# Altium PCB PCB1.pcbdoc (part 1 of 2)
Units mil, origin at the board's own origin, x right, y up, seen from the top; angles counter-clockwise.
Board outline 4100 x 4075 mil, 2 copper layers (Top Layer, Bottom Layer); 99 components, 67 nets, 330 pads, 1473 vias.
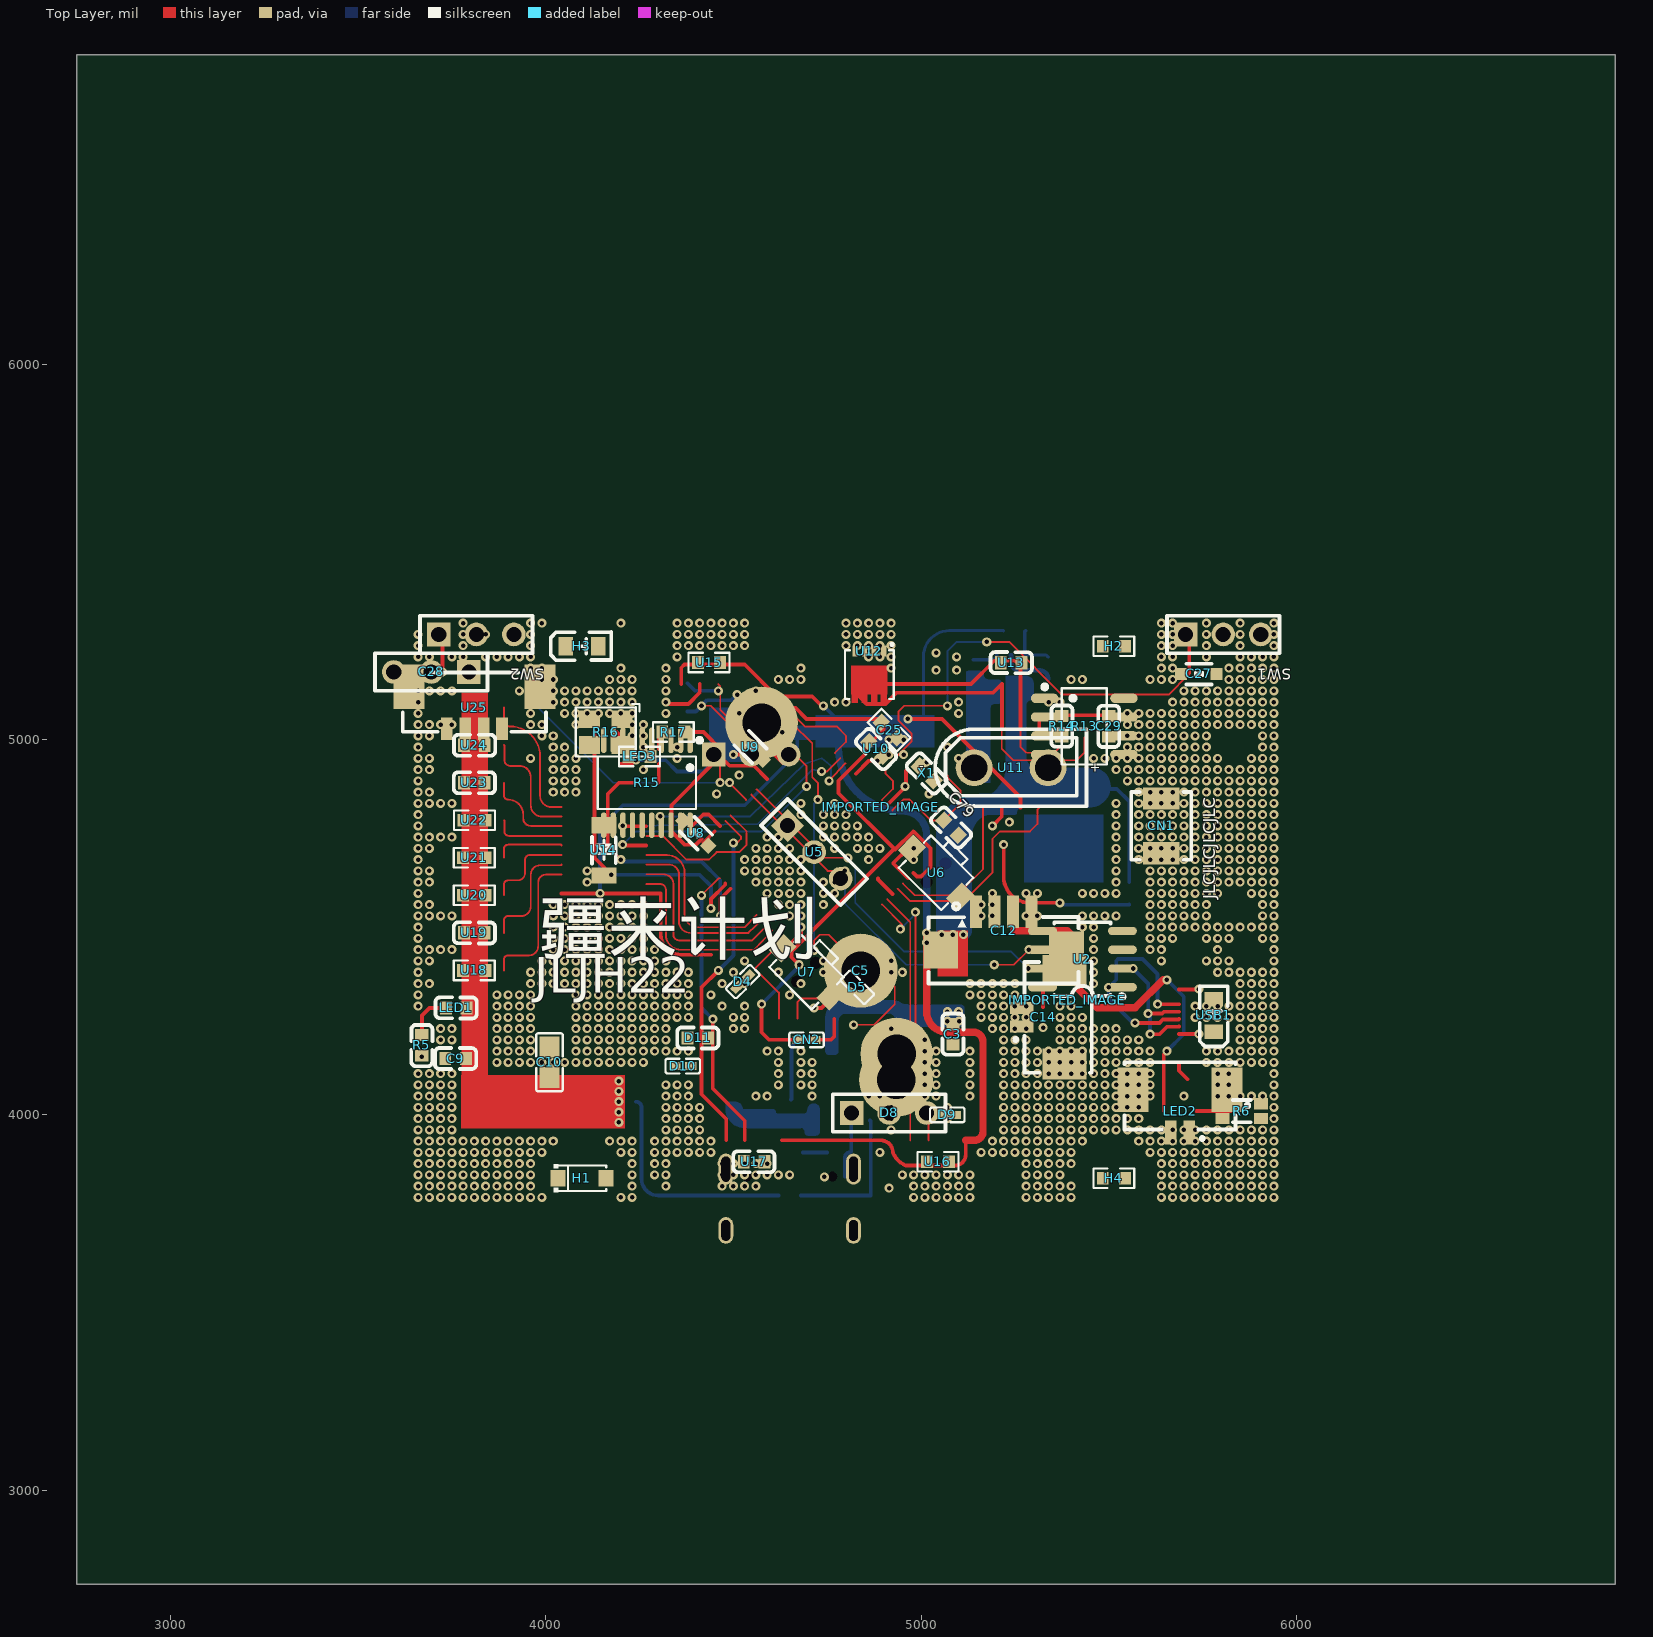
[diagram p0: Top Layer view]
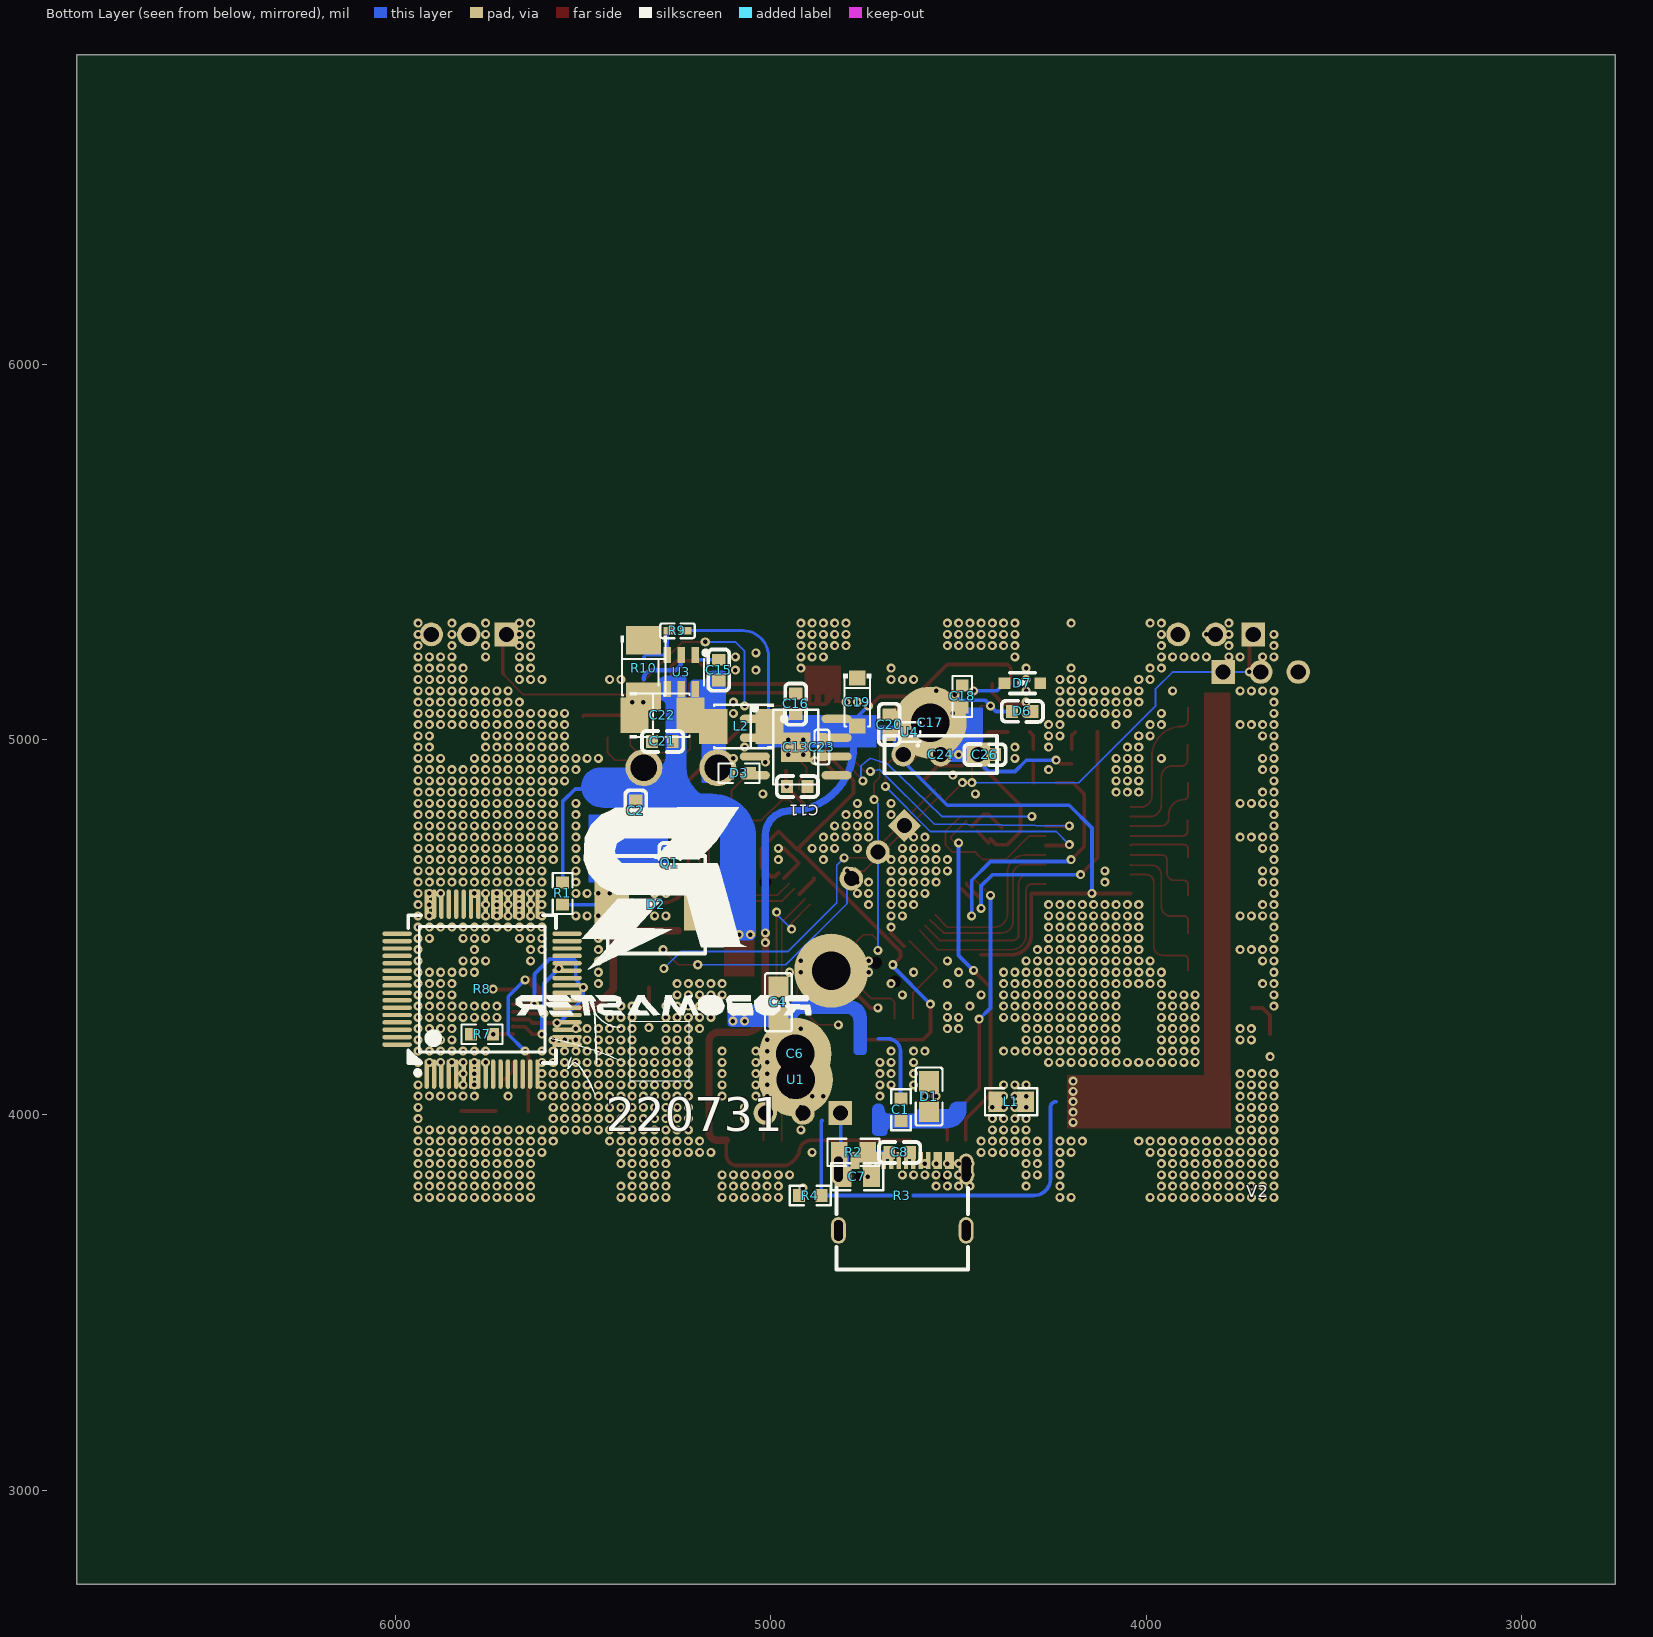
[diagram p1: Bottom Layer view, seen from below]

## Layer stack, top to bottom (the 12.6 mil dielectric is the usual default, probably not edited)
Top Solder: solder mask 0.4, Solder Resist, Dk 3.5
Top Layer: signal copper 1.4
Dielectric 1: dielectric 12.6, FR-4, Dk 4.8
Bottom Layer: signal copper 1.4
Bottom Solder: solder mask 0.4, Solder Resist, Dk 3.5

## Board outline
6850,2750 2750,2750 2750,6825 6850,6825

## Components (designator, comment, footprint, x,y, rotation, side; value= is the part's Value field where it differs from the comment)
C1 "CC0603KRX7R9BB104" R0603 4653.7,4013.7 r270 bottom
C2 "CL10B104KC8NNNC" C0603 5360,4810 r90 bottom
C3 "VT1E101M-CRE54" C0603 5085,4215 r270 top
C4 "CC0603KRX7R9BB104" C0805 4980,4300 r270 bottom
C5 "CL10B104KC8NNNC" M2.5#1 4885,4430 r225 top
C6 "0603B822J500CT" M2.5#2 4935,4162.44 r90 bottom
C7 "CC0603GRNPO9BN100" R0805 4770,3835 r0 bottom
C8 "CL10B102KB8NNNC" C0603 4657.44,3900 r0 bottom
C9 "CC0603KRX7R9BB104" C0603 3760,4150 r0 top
C10 "VT1E101M-CRE54" C0805 4010,4140 r90 top
C11 "0603CG200G500NT" C0603 4930,4875 r0 bottom
C12 "TCC0603X7R104K500CT" CONN-SMD_4P-P1.25_SHOUHAN_1.25-4PWTDK 5220,4490 r0 top
C13 "GRT188C80J226ME13D" SOIC-8_L5.0-W4.0-P1.27-LS6.0-BL-EP2.0 4934.03,4979.87 r270 bottom
C14 "TCC0603X7R104K500CT" CONN-SMD_2P-P1.25_SHOU_1.25-2PWTDK 5325,4260 r90 top
C15 "CL10B104KC8NNNC" C0603 5139.03,5184.87 r270 bottom
C16 "GRM155R71E104KE14D" C0603 4934.03,5094.87 r90 bottom
C17 "CGA2B3X7R1V104MT0Y0F" M2.5#2 4575,5045 r270 bottom
C18 "TC211B106K025Y" R0603 4490,5114.8 r270 bottom
C19 "TC211B106K025Y" SOD-123_L2.7-W1.8-LS3.7-RD 4770,5100 r270 bottom
C20 "CGA2B3X7R1V104MT0Y0F" C0603 4685,5040 r270 bottom
C21 "GRM188C81E475KE11D" C0603 5289.03,4994.87 r0 bottom
C22 "CL10B104KC8NNNC" CAP-SMD_L3.5-W2.8-R-RD 5289.03,5064.87 r0 bottom
C23 "GCM1885C2A220JA16D" C0402 4864.03,4979.87 r270 bottom
C24 "0603" HDR-TH_3P-P2.54-V-M_C9900004029 4547.56,4960 r180 bottom
C25 "0603" R0603 4915,5025 r135 top
C26 "0603" C0603 4430,4960 r0 bottom
C27 "100nF" SOD-323_L1.7-W1.3-LS2.5-BI 5740,5175 r180 top
C28 "100nF" HDR-TH_3P-P2.54-V-M_C9900004029 3695,5180 r0 top
C29 "CL10B104KC8NNNC" C0603 5500,5035 r270 top
C79 "0603CG200G500NT" C0603 5080,4765 r315 top
CN1 "XT30PW-M" IND-SMD_L4.5-W4.0-1 5640,4770 r90 top
CN2 "X9821WVS-04-9TSN" C0402 4695,4200 r0 top
D1 "DSK310" C0805 4578.7,4048.7 r90 bottom
D2 "ZMM9V1" IND-SMD_L6.6-W6.6 5305,4560 r180 bottom
D3 "DSK310" R0603 5085,4910 r180 bottom
D4 "PESD5V0L1BA" C0402 4525,4355 r225 top
D5 "PESD5V0L1BA" C0402 4830,4340 r315 top
D6 "PESD5V0L1BA" C0603 4330,5075 r180 bottom
D7 "PESD5V0L1BA" SOD-323_L1.7-W1.3-LS2.5-BI 4330,5150 r180 bottom
D8 "PESD5V0L1BA" HDR-TH_3P-P2.54-V-M_C9900004029 4915,4005 r180 top
D9 "PESD5V0L1BA" C0402 5070,4000 r0 top
D10 "PESD5V0L1BA" C0402 4365,4130 r180 top
D11 "PESD5V0L1BA" C0603 4405,4205 r180 top
H1 "M2.5_M2.5" SOD-123_L2.7-W1.8-LS3.7-RD 4096.34,3831.34 r0 top
H2 "M2.5_M2.5" R0603 5513.66,5248.66 r0 top
H3 "M2.5_M2.5" LED0805-RD_RED 4096.34,5248.66 r0 top
H4 "M2.5_M2.5" R0603 5513.66,3831.34 r0 top
IMPORTED_IMAGE "IMPORTED_IMAGE" IMPORTED_IMAGE 5390,4305 r0 top
IMPORTED_IMAGE "IMPORTED_IMAGE" IMPORTED_IMAGE 4892.04,4820.19 r0 top
L1 "SMMS0630-6R8M" R0805 4360,4035 r180 bottom
L2 "MCS0420-4R7MPN2" CAP-SMD_L3.5-W2.8-R-RD 5079.03,5034.87 r180 bottom
LED1 "NCD0805R1" C0603 3761.69,4285 r0 top
LED2 "NCD0805R1" CONN-SMD_2P-P1.25_SHOU_1.25-2PWTDK 5690,4010 r180 top
LED3 "HL-PCF-3216S39FU70GH203BC-A" R0603 4250,4955 r0 top
Q1 "WSD3066DN33" C0603 5269.31,4669.9 r90 bottom
R1 "AR03BTD1002" R0603 5555,4590 r90 bottom
R2 "RS-03K473JT" R0805 4780,3900 r180 bottom
R3 "TC0325B4022T5E" USB-C-SMD_TYPE-C16PIN 4650,3785 r180 bottom
R4 "RMC06037.68K1%N" R0603 4895.34,3785 r180 bottom
R5 "RMC06035.1K1%N" C0603 3670,4185 r90 top
R6 "RMC06035.1K5%N" LED-SMD_4P-L3.2-W1.5-BL 5854.66,4010 r180 top
R7 "RMC06035.1K1%N" R0603 5769.66,4215 r180 bottom
R8 "RMC06035.1K1%N" LQFP-64_L10.0-W10.0-P0.50-LS12.0-BL 5769.66,4335 r180 bottom
R9 "TC0325B4022T5E" C0402 5249.03,5289.87 r180 bottom
R10 "RMC06037.68K1%N" CAP-SMD_L3.5-W2.8-R-RD 5339.03,5189.87 r90 bottom
R13 "CR0603JA0560G" SOP-8_L4.9-W3.9-P1.27-LS6.0-BL 5435,5035 r270 top
R14 "CR0603JA0560G" C0603 5375,5035.34 r270 top
R15 "ACPP0603 51R B" TSSOP-20_L6.5-W4.4-P0.65-LS6.4-BL 4269.66,4885 r180 top
R16 "ACPP0603 51R B" OSC-SMD_4P-L3.2-W2.5-BL 4159.66,5020 r180 top
R17 "ACPP0603 51R B" R0603 4340,5020 r0 top
SW1 "YD-3410" HDR-TH_3P-P2.54-V-M_C9900004029 5805,5280 r180 top
SW2 "YD-3410" HDR-TH_3P-P2.54-V-M_C9900004029 3815,5280 r180 top
U1 "TPS54531DDAR" M2.5#3 4788.7,4093.7 r0 bottom
U2 "CH340N" SOIC-8_L5.0-W4.0-P1.27-LS6.0-BL 5430,4415 r90 top
U3 "RY8411" SOT-23-6_L2.9-W1.6-P0.95-LS2.8-TL 5239.03,5179.87 r270 bottom
U4 "SK6019AD4-33" XDFN-4_L1.0-W1.0-P0.65-BL-EP 4630,5020 r90 bottom
U5 "STM32L431RCT6" HDR-TH_3P-P2.54-V-M_C9900004029 4715,4700 r135 top
U6 "CAP,MLCC,X7R,100nF,10V,10%,SMD0402,ROHS" SW-SMD_L3.9-W2.9-LS4.8-EH-A 5040,4645 r135 top
U7 "CAP,MLCC,X7R,100nF,10V,10%,SMD0402,ROHS" SW-SMD_L3.9-W2.9-LS4.8-EH-A 4694.83,4380.17 r135 top
U8 "CAP,MLCC,X7R,100nF,10V,10%,SMD0402,ROHS" SOD-323_L1.7-W1.3-LS2.5-BI 4400,4750 r315 top
U9 "CAP,MLCC,X7R,100nF,10V,10%,SMD0402,ROHS" SOD-323_L1.7-W1.3-LS2.5-BI 4545,4980 r315 top
U10 "CAP,MLCC,X7R,100nF,10V,10%,SMD0402,ROHS" C0603 4880,4975 r135 top
U11 "TJA1040T/CM,118" CONN-TH_XT30UPB-M 5240,4925 r0 top
U12 "1.25-2PWTDK" DFN-8_L3.3-W3.3-P0.65-BL 4862.1,5205 r180 top
U13 "1.25-2PWTDK" C0603 5240,5205 r180 top
U14 "74HC245PW" LL-34_L3.5-W1.5-RD 4155,4705 r90 top
U15 "1.25-4PWTDK" R0603 4435,5205 r180 top
U16 "1.25-4PWTDK" R0603 5045,3875 r0 top
U17 "1.25-4PWTDK" C0603 4555,3875 r0 top
U18 "3pin插件排针" R0603 3809.64,4385 r180 top
U19 "3pin插件排针" C0603 3809.64,4485 r180 top
U20 "3pin插件排针" R0603 3809.64,4585 r180 top
U21 "3pin插件排针" R0603 3809.64,4685 r180 top
U22 "3pin插件排针" R0603 3810,4785 r180 top
U23 "3pin插件排针" C0603 3809.64,4885 r180 top
U24 "3pin插件排针" C0603 3810,4985 r180 top
U25 "3pin插件排针" CONN-SMD_4P-P1.25_X9821WVS-04-9TSN 3810,5085 r180 top
USB1 "TYPE-C 16PIN 3MD(385)" LED0805-RD_RED 5780,4265 r90 top
X1 "X32258MOB4SI" C0603 5015,4910 r135 top

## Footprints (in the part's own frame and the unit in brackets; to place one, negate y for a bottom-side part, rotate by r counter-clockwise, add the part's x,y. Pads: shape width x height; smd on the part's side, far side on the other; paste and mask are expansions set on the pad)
C0402 [mm]
  rect 0.79x0.54 smd: 1(-0.545,0) 2(0.545,0)
  silkscreen extent -1.17,-0.5 1.17,0.5
C0603 [mm]
  rect 0.8x0.9 smd: 1(-0.7,0) 2(0.7,0)
  silkscreen extent -1.41,-0.71 1.39,0.72
C0805 [mm]
  rect 1.41x1.35 smd: 1(-1.03,0) 2(1.03,0)
  silkscreen extent -1.96,-0.9 1.96,0.9
CAP-SMD_L3.5-W2.8-R-RD [mil]
  rect 74.8x93.5 smd: 1(74.8,0) 2(-74.7,0)
  silkscreen extent -72,-61 87,61
CONN-SMD_2P-P1.25_SHOU_1.25-2PWTDK [mm]
  rect 0.8x1.6 smd: 1(-0.625,1.45) 2(0.625,1.45)
  rect 2.1x3 smd: 3(3.175,-1.45) 4(-3.175,-1.45)
  silkscreen extent -3.75,-3.3 3.75,1.95
CONN-SMD_4P-P1.25_SHOUHAN_1.25-4PWTDK [mm]
  rect 0.8x2.2 smd: 1(-1.875,1.3) 2(-0.625,1.3) 3(0.625,1.3) 4(1.875,1.3)
  rect 2.35x2.5 smd: 5(4.255,-1.3) 6(-4.255,-1.3)
  silkscreen extent -5.08,-3.55 5.06,1.88
CONN-SMD_4P-P1.25_X9821WVS-04-9TSN [mil]
  rect 31.5x59.1 smd: 1(-73.8,56.1) 2(-24.6,56.1) 3(24.6,56.1) 4(73.8,56.1)
  rect 82.7x118.1 smd: 5(174.2,-56.1) 6(-174.2,-56.1)
  silkscreen extent -191,-94 191,64
CONN-TH_XT30UPB-M [mil]
  round 98.4 hole 70.9: 1(-98.4,0) 2(98.4,0)
  silkscreen extent -202,-102 201,102
DFN-8_L3.3-W3.3-P0.65-BL [mm]
  rect 0.35x0.75 smd: 1(-0.975,-0.78) 2(-0.325,-0.78) 3(0.325,-0.78) 4(0.975,-0.78)
  Top Layer region: -1.222,0.201 -1.222,2.129 -1.174,2.129 -1.174,2.73 -0.773,2.73 -0.773,2.129 -0.524,2.129 -0.524,2.73 -0.123,2.73 -0.123,2.129 0.126,2.129 0.126,2.73 0.528,2.73 0.528,2.129 0.777,2.129 0.777,2.73 0.777,2.129 0.777,2.73 1.178,2.73 1.178,2.129 1.226,2.129 1.226,0.201
  silkscreen extent -1.65,-1.27 1.65,2.46
HDR-TH_3P-P2.54-V-M_C9900004029 [mil]
  rect 63x63 hole 40.2: 1(100,0)
  round 63 hole 40.2: 2(0,0) 3(-100,0)
  silkscreen extent -150,-50 150,50
IMPORTED_IMAGE [mil]
IND-SMD_L4.5-W4.0-1 [mil]
  rect 59.1x98.4 smd: 1(-72.8,0) 2(72.8,0)
  silkscreen extent -90,-80 90,80
IND-SMD_L6.6-W6.6 [mil]
  rect 92.5x137.8 smd: 1(-119.5,0) 2(119.5,0)
  silkscreen extent -130,-130 130,130
LED0805-RD_RED [mm]
  rect 1x1.25 smd: 1(-1.1,0) 2(1.1,0)
  silkscreen extent -2.1,-0.95 1.98,0.96
LED-SMD_4P-L3.2-W1.5-BL [mm]
  rect 0.95x0.75 smd: 1(1.3,-0.5) 2(-1.3,-0.5) 3(-1.3,0.5) 4(1.3,0.5)
  silkscreen extent -0.59,-0.76 0.59,0.75
LL-34_L3.5-W1.5-RD [mil]
  rect 43.3x66.9 smd: 1(-66.9,0) 2(66.9,0)
  silkscreen extent -35,-32 35,32
LQFP-64_L10.0-W10.0-P0.50-LS12.0-BL [mm]
  oval 0.3x2 smd: 1(-3.75,-5.75) 2(-3.25,-5.75) 3(-2.75,-5.75) 4(-2.25,-5.75) 5(-1.75,-5.75) 6(-1.25,-5.75) 7(-0.75,-5.75) 8(-0.25,-5.75) 9(0.25,-5.75) 10(0.75,-5.75) 11(1.25,-5.75) 12(1.75,-5.75) 13(2.25,-5.75) 14(2.75,-5.75) 15(3.25,-5.75) 16(3.75,-5.75) 33(3.75,5.75) 34(3.25,5.75) 35(2.75,5.75) 36(2.25,5.75) 37(1.75,5.75) 38(1.25,5.75) 39(0.75,5.75) 40(0.25,5.75) 41(-0.25,5.75) 42(-0.75,5.75) 43(-1.25,5.75) 44(-1.75,5.75) 45(-2.25,5.75) 46(-2.75,5.75) 47(-3.25,5.75) 48(-3.75,5.75)
  oval 2x0.3 smd: 17(5.75,-3.75) 18(5.75,-3.25) 19(5.75,-2.75) 20(5.75,-2.25) 21(5.75,-1.75) 22(5.75,-1.25) 23(5.75,-0.75) 24(5.75,-0.25) 25(5.75,0.25) 26(5.75,0.75) 27(5.75,1.25) 28(5.75,1.75) 29(5.75,2.25) 30(5.75,2.75) 31(5.75,3.25) 32(5.75,3.75) 49(-5.75,3.75) 50(-5.75,3.25) 51(-5.75,2.75) 52(-5.75,2.25) 53(-5.75,1.75) 54(-5.75,1.25) 55(-5.75,0.75) 56(-5.75,0.25) 57(-5.75,-0.25) 58(-5.75,-0.75) 59(-5.75,-1.25) 60(-5.75,-1.75) 61(-5.75,-2.25) 62(-5.75,-2.75) 63(-5.75,-3.25) 64(-5.75,-3.75)
  silkscreen extent -5,-5.79 5,5
M2.5#1 [mm]
  round 5 hole 2.6: 1(1.645,0)
M2.5#2 [mm]
  round 4.9 hole 2.6: 1(0,0)
M2.5#3 [mm]
  round 5 hole 2.6: 1(3.677,0)
OSC-SMD_4P-L3.2-W2.5-BL [mm]
  rect 1.4x1.2 smd: 1(-1.1,-0.875) 2(1.1,-0.875) 3(1.1,0.875) 4(-1.1,0.875)
  silkscreen extent -2.29,-1.9 2.03,1.65
R0603 [mil]
  rect 31.75x34.02 smd: 1(-29.66,0) 2(29.66,0)
  silkscreen extent -55,-26 55,26
R0805 [mil]
  rect 44.59x54.21 smd: 1(-38.04,0) 2(38.04,0)
  silkscreen extent -69,-36 69,36
SOD-123_L2.7-W1.8-LS3.7-RD [mil]
  rect 39.4x43.3 smd: 1(-64,0) 2(64.1,0)
  silkscreen extent -75,-37 65,37
SOD-323_L1.7-W1.3-LS2.5-BI [mil]
  rect 31.5x31.5 smd: 1(-47.4,0) 2(47.4,0)
  silkscreen extent -34,-27 33,28
SOIC-8_L5.0-W4.0-P1.27-LS6.0-BL [mil]
  oval 22.38x76.78 smd: 1(-75,-106.5) 2(-25,-106.5) 3(25,-106.5) 4(75,-106.5) 5(75,106.5) 6(25,106.5) 7(-25,106.5) 8(-75,106.5)
  silkscreen extent -106,-111 98,75
SOIC-8_L5.0-W4.0-P1.27-LS6.0-BL-EP2.0 [mil]
  oval 22.6x80.2 smd: 1(-75,-109) 2(-25,-109) 3(25,-109) 4(75,-109) 5(75,109) 6(25,109) 7(-25,109) 8(-75,109)
  rect 78.7x78.7 smd: 9(0,0)
  silkscreen extent -110,-115 100,60
SOP-8_L4.9-W3.9-P1.27-LS6.0-BL [mm]
  oval 0.63x1.865 smd: 1(-1.905,-2.682) 2(-0.635,-2.682) 3(0.635,-2.682) 4(1.905,-2.682) 5(1.905,2.682) 6(0.635,2.682) 7(-0.635,2.682) 8(-1.905,2.682)
  silkscreen extent -2.82,-2.83 2.58,1.52
SOT-23-6_L2.9-W1.6-P0.95-LS2.8-TL [mil]
  rect 42.2x20.9 smd: 1(-45.2,37.4) 2(-45.2,0) 3(-45.2,-37.4) 4(45.2,-37.4) 5(45.2,0) 6(45.2,37.4)
  silkscreen extent -57,-61 35,72
SW-SMD_L3.9-W2.9-LS4.8-EH-A [mil]
  rect 48.4x59.1 smd: 1(-90.5,0) 2(90.6,0)
  Multi-Layer board cut-out: -11.1,-46.5 -5.19,-50.22 1.76,-51 8.35,-48.69 13.29,-43.75 15.6,-37.16 14.82,-30.21 11.1,-24.3 11.1,-24.3 5.19,-20.58 -1.76,-19.8 -8.35,-22.11 -13.29,-27.05 -15.6,-33.64 -14.82,-40.59 -11.1,-46.5
  Multi-Layer board cut-out: -11.1,24.3 -5.19,20.58 1.76,19.8 8.35,22.11 13.29,27.05 15.6,33.64 14.82,40.59 11.1,46.5 11.1,46.5 5.19,50.22 -1.76,51 -8.35,48.69 -13.29,43.75 -15.6,37.16 -14.82,30.21 -11.1,24.3
  silkscreen extent -80,-85 80,61
TSSOP-20_L6.5-W4.4-P0.65-LS6.4-BL [mil]
  oval 14.33x68.58 smd: 1(-115.16,-113.03) 2(-89.57,-113.03) 3(-63.98,-113.03) 4(-38.39,-113.03) 5(-12.79,-113.03) 6(12.8,-113.03) 7(38.39,-113.03) 8(63.98,-113.03) 9(89.57,-113.03) 10(115.16,-113.03) 11(115.16,113.03) 12(89.57,113.03) 13(63.98,113.03) 14(38.39,113.03) 15(12.8,113.03) 16(-12.79,113.03) 17(-38.39,113.03) 18(-63.98,113.03) 19(-89.57,113.03) 20(-115.16,113.03)
  silkscreen extent -146,-119 131,70
USB-C-SMD_TYPE-C16PIN [mil]
  oval 39.4x82.7 hole 23.6 slot 66.9 at 90 deg: 1(-170.1,70.4) 2(170.1,70.4)
  oval 39.4x70.9 hole 23.6 slot 55.1 at 90 deg: 3(-170.1,-93) 4(170.1,-93)
  rect 23.6x45.3 smd: A1B12(-126,93) A4B9(-94.5,93) B1A12(126,93) B4A9(94.5,93)
  rect 11.8x45.3 smd: A5(-49.2,93) A6(-9.8,93) A7(9.8,93) A8(-68.9,93) B5(68.9,93) B6(29.5,93) B7(-29.5,93) B8(49.2,93)
  Multi-Layer board cut-out: 101,50.7 102.27,56.25 105.82,60.71 110.95,63.18 116.65,63.18 121.78,60.71 125.33,56.25 126.6,50.7 126.6,50.7 125.33,45.15 121.78,40.69 116.65,38.22 110.95,38.22 105.82,40.69 102.27,45.15 101,50.7
  Multi-Layer board cut-out: -126.6,50.7 -125.33,56.25 -121.78,60.71 -116.65,63.18 -110.95,63.18 -105.82,60.71 -102.27,56.25 -101,50.7 -101,50.7 -102.27,45.15 -105.82,40.69 -110.95,38.22 -116.65,38.22 -121.78,40.69 -125.33,45.15 -126.6,50.7
  silkscreen extent -175,-197 175,20
XDFN-4_L1.0-W1.0-P0.65-BL-EP [mm]
  rect 0.45x0.45 smd rot 45: 5(0,0)
  Top Layer region: 0.425,-0.65 0.225,-0.65 0.225,-0.4 0.375,-0.25 0.425,-0.25
  Top Layer region: -0.425,0.65 -0.225,0.65 -0.225,0.4 -0.375,0.25 -0.425,0.25
  Top Layer region: 0.425,0.65 0.225,0.65 0.225,0.4 0.375,0.25 0.425,0.25
  Top Layer region: -0.225,-0.4 -0.225,-0.65 -0.425,-0.65 -0.425,-0.2 -0.375,-0.25
  silkscreen extent -0.98,-0.7 0.66,0.7

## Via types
v1: diameter 24, hole 12, Top Layer to Bottom Layer, 1389 vias
v2: diameter 24.02, hole 12.01, Top Layer to Bottom Layer, 83 vias
v3: diameter 20.08, hole 12.01, Top Layer to Bottom Layer, 1 vias

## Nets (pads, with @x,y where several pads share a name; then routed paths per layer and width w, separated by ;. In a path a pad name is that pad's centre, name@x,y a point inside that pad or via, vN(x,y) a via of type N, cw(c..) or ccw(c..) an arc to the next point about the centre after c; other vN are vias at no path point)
3V3: LED3.2 U5.1 | length 2821.6
  Top Layer w10: 4198.82,4935.31 4230.31,4935.31 v2(4240,4945) ; 4415.17,4734.83 4400.35,4720 4370,4720 4335,4755 4335,4825 4450,4940 4450,4945 v2(4445,4950) ; 4420.17,4725.17 4450.53,4755.53 4450.53,4755.67 ; v2(4500,4960) 4555.35,4960 4560.17,4964.83 4603.29,4964.83 4631.49,4936.63 ; v2(4515,5070) 4530,5085 4665,5085 4695,5055 4885,5055 4900.51,5039.49 4900.51,5025.86 4864.83,4990.17 4850,4975.35 4850,4960.27 4812.43,4922.7 4780,4890.27 4780,4857.13 4930.46,4706.67 ; v2(4575,4295) 4575,4220 4595,4200 4760,4200 4768.8,4208.8 4768.8,4256.1 ; v2(4675,4400) 4655,4420 4655,4435.14 4926.53,4706.67 4930.46,4706.67 ; 4979.47,4644.33 4988.79,4635 5000,4635 5010,4645 5010,4645.35 5024.83,4660.17 5024.83,4710.31 4979.47,4755.67 4930.46,4706.67
  Bottom Layer w10: v2(4240,4945) 4320,4945 4350,4915 4420,4915 4445,4940 v2(4445,4950) ; v2(4575,4295) 4675,4395 v2(4675,4400)
5V: C13.1 C16.1 C23.1 | length 4677.5
  Top Layer w10: 4041.97,4589.84 v2(4144.66,4589.84) 4268.03,4589.84 4306.5,4589.84 4306.5,4480 ccw(c4360,4480) 4360,4426.5 4440,4426.5 ; 4361.18,5147.91 4361.18,5191.18 4370,5200 4530,5200 4615,5115 4710,5115 4735,5090 v2(4740,5090) ; 4628.82,3932.09 4892.91,3932.09 cw(c4892.91,3900) 4925,3900 ccw(c4984.75,3924.75) 4960,3865 5090,3865 ccw(c5090,3893.82) 5118.82,3893.82 5118.82,3932.09 ; v2@4970,5055 5055.7,5055 5265,4845.7 5265,4818.5
  Top Layer w19.68: v2(5015,4485) v2(5015,4459.06) 5015,4275 ccw(c5070,4275) 5070,4220 5140,4220 cw(c5140,4195) 5165,4195 5165,3955 cw(c5142.09,3955) 5142.09,3932.09 5118.82,3932.09
  Bottom Layer w8: 5006.23,5034.87 5006.23,5221.23 cw(c5075,5221.23) 5075,5290 5219.23,5290 cw(c5219.23,5289.87) 5219.37,5289.87
  Bottom Layer w10: v2(4144.66,4589.84) 4144.66,4764.66 4205,4825 4530,4825 4670,4965 4670,5015 ; v2(4740,5090) 4770,5060 4770,5025.2
  Bottom Layer w19.68: 4780.03,4976.8 ccw(c4950,4980) 4950,4810 cw(c4950,4745) 5015,4745 v2(5015,4485)
  other v2: 4965,5055
$1N3621: L2.1
$1N4618: D2.1 R1.1 | length 458.2
  Top Layer w10: v2(5220,4720) 5220,4635 ccw(c5290,4635) 5290,4565 v2(5370,4565)
  Bottom Layer w10: v2@5371.9,4560 5554.66,4560 R1.1@5555,4560.34
$1N5688: C15.1 U3.1 | length 69.8
  Bottom Layer w10: C15.1@5139.03,5212.43 5188.99,5212.43 ccw(c5188.99,5225.07) U3.1@5201.63,5225.07
$1N9912:  | length 65.3
  Bottom Layer w10: 4685,3900 4750.34,3900
$1N9916: LED1.1 | length 107
  Top Layer w10: 3670,4214.66 3670,4265 3690,4285 3718.38,4285
$1N9919: 
$1N9922:  | length 76.6
  Bottom Layer w10: 4863.7,4202.7 4876.4,4190 4935,4190
$1N9925: C1.1 | length 206.8
  Bottom Layer w10: C1.1@4653.7,4041.26 ccw(c4653.7,4042.56) 4655,4042.56 4655,4170 cw(c4687.7,4170) 4687.7,4202.7 4713.7,4202.7
$1N9926: R2.1 | length 158.9
  Bottom Layer w10: 4797.56,3835 4797.56,3887.9 cw(c4809.66,3887.9) 4809.66,3900 ccw(c4809.66,3904.04) 4813.7,3904.04 4813.7,3984.7
$1N15560: C29.1 R13.1 R14.1 | length 213.7
  Top Layer w10: 5315,5031.5 5315,5055 5325,5065 5375,5065 5434.66,5065 5435,5064.66 5497.9,5064.66 C29.1@5500,5062.56
$1N19092:  | length 53.5
  Top Layer w10: 5687,4333.9 5738.9,4333.9 v2(5740,4335)
$1N19093:  | length 53.3
  Top Layer w10: 5687,4215.8 5739.2,4215.8 v2(5740,4215)
$1N19102: U2.8 | length 52.7
  Top Layer w10: U2.8@5324.39,4340 5325,4339.39 5325,4287.56
$1N19108: LED2.1 | length 91.7
  Top Layer w10: 5733.31,4010 5825,4010
$1N20010: R15.1 | length 51.1
  Top Layer w10: 4299.32,4885 4301.18,4886.86 4301.18,4935.31
$1N20185: R16.1 | length 49.3
  Top Layer w10: 4189.32,5020 4198.82,5010.5 4198.82,4974.69
$1N20360: R17.1 | length 49.1
  Top Layer w10: 4301.18,4974.69 4301.18,5010.84 R17.1@4310.34,5020
BAT-: C2.1
CAN_H: U12.2 U13.2 | length 896.6
  Top Layer w5: 5215,5031.5 5215,4975 5245,4945 5415,4945 5435,4965 5435,5005.34
  Top Layer w10: 4837.5,5147.91 4837.5,5112.5 4855,5095 4905,5095 4935,5125 5192.48,5125 5215.39,5147.91 5215.39,5031.89 5215,5031.5
CAN_L:  | length 770.4
  Top Layer w5: 5265,5031.5 5265,4980 5280,4965 5355,4965 5375,4985 5375,5005.68
  Top Layer w10: 4886.71,5147.91 5132.91,5147.91 5195,5210 5250,5210 5264.6,5195.4 5264.6,5147.91 5265,5147.52 5265,5031.5
CAN_RX:  | length 569
  Top Layer w5: 4937.7,4602.57 4970.27,4570 5115,4570 5190,4645 5190,4735 5210,4755 5290,4755 5310,4775 5310,4813.5 5315,4818.5
CAN_TX:  | length 418.9
  Top Layer w5: 4951.63,4616.49 4983.12,4585 5095,4585 5165,4655 5165,4818.5
DN: U2.2 | length 363.1
  Top Layer w10: v2(5605,4270) 5642.55,4270 5647.35,4274.8 5687,4274.8 ; v2(5610,4215) 5635,4215 5655,4235 5686.5,4235 5687,4235.5
  Bottom Layer w10: v2(5565,4390) 5605,4350 v2(5605,4270) 5610,4265 v2(5610,4215)
DP:  | length 592.3
  Top Layer w10: v2(5570,4245) 5635,4245 5644.07,4254.07 5685.87,4254.07 5687,4255.2 ; v2(5630,4295) 5686.5,4295 5687,4294.5
  Bottom Layer w10: v2(5570,4245) 5565,4245 5500,4310 v2(5500,4340) 5520,4360 5520,4410 5525,4415 5590,4415 5630,4375 v2(5630,4295)
FB: R9.1 U3.3 | length 130.6
  Bottom Layer w8: U3.3@5276.43,5225.07 5333.49,5225.07 5339.03,5219.53
  Bottom Layer w10: U3.3@5276.43,5225.07 5276.43,5287.61 R9.1@5278.69,5289.87
GND: C4.1 C5.1 C6.1 C7.1 C8.1 C9.1 C11.1 C12.1 C14.1 C17.1 C18.2 C19.2 C20.1 C24.1 C25.1 C26.1 C27.1 C28.1 D1.2 D3.2 Q1.1 Q1.2 R4.1 R5.1 R6.1 R7.1 R8.1 R10.1 SW1.1 SW2.1 U1.1 U2.3 U3.2 U6.1 U7.1 U8.1 U9.1 U10.1 U11.2 U12.3 U12.4 U25.3 USB1.1 USB1.2 X1.2 | length 1069.5
  Top Layer w10: v1(4320,5100) 4325,5095 4380,5095 4410.39,5125.39 4410.39,5147.91 ; 4384.83,4765.17 4419.65,4800 4434.05,4800 4464.46,4769.59 ; v3(4630,5020) 4620,5020 4605,5005 4605,4990.95 4645.41,4950.54 ; 4645.41,4449.46 4680,4484.05 v1(4680,4500) ; v2(4715,4285) 4735,4285 4765,4315 4815,4315 4830,4330 v1(4830,4350) ; 4826.35,4908.79 4861.39,4943.82 v2(4883.41,4943.82) ; 4885,4630 4885,4627.44 4923.79,4588.65 ; 4965.54,4630.41 4925.6,4670.35 4925.6,4670.6 4965,4710 v1(4980,4710) ; v1(5190,4770) 5215,4795 5215,4818.5 ; 5687,4139 5687,4117.5 5709.6,4094.9
  Bottom Layer w12: U3.2@5239.03,5225.07 cw(c5239.03,5224.09) 5240,5224.09 5240,5200 ccw(c5265.61,5210.61) 5255,5185 5314.23,5185 cw(c5314.23,5160.21) 5339.03,5160.21
  other v1: 3660,3780 3690,3780 3720,3780 3750,3780 3780,3780 3810,3780 3840,3780 3870,3780 3900,3780 3930,3780 3960,3780 3990,3780 4200,3780 4230,3780 4980,3780 5010,3780 5040,3780 5070,3780 5100,3780 5130,3780 5280,3780 5310,3780 5340,3780 5370,3780 5400,3780 5640,3780 5670,3780 5700,3780 5730,3780 5760,3780 5790,3780 5820,3780 5850,3780 5880,3780 5910,3780 5940,3780 3660,3810 3690,3810 3720,3810 3750,3810 3780,3810 3810,3810 3840,3810 3870,3810 3900,3810 3930,3810 3960,3810 4230,3810 4320,3810 4470,3810 4500,3810 4530,3810 4560,3810 4980,3810 5010,3810 5040,3810 5070,3810 5100,3810 5130,3810 5280,3810 5310,3810 5340,3810 5370,3810 5400,3810 5640,3810 5670,3810 5700,3810 5730,3810 5760,3810 5790,3810 5820,3810 5850,3810 5880,3810 5910,3810 5940,3810 3660,3840 3690,3840 3720,3840 3750,3840 3780,3840 3810,3840 3840,3840 3870,3840 3900,3840 3930,3840 3960,3840 4230,3840 4290,3840 4320,3840 4470,3840 4500,3840 4530,3840 4560,3840 4590,3840 4620,3840 4650,3840 4950,3840 4980,3840 5010,3840 5040,3840 5070,3840 5100,3840 5130,3840 5280,3840 5310,3840 5340,3840 5370,3840 5640,3840 5670,3840 5700,3840 5730,3840 5760,3840 5790,3840 5820,3840 5850,3840 5880,3840 5910,3840 5940,3840 3660,3870 3690,3870 3720,3870 3750,3870 3780,3870 3810,3870 3840,3870 3870,3870 3900,3870 3930,3870 3960,3870 4230,3870 4290,3870 4320,3870 4470,3870 4500,3870 4530,3870 4560,3870 4590,3870 5280,3870 5310,3870 5340,3870 5370,3870 5400,3870 5640,3870 5670,3870 5700,3870 5730,3870 5760,3870 5790,3870 5820,3870 5850,3870 5880,3870 5910,3870 5940,3870 3660,3900 3690,3900 3720,3900 3750,3900 3780,3900 3810,3900 3840,3900 3870,3900 3900,3900 3930,3900 3960,3900 3990,3900 4200,3900 4230,3900 4290,3900 4320,3900 4350,3900 4380,3900 4410,3900 4440,3900 4890,3900 5160,3900 5190,3900 5220,3900 5250,3900 5280,3900 5310,3900 5340,3900 5370,3900 5400,3900 5610,3900 5640,3900 5670,3900 5700,3900 5730,3900 5760,3900 5790,3900 5820,3900 5850,3900 5880,3900 5910,3900 5940,3900 3660,3930 3690,3930 3720,3930 3750,3930 3780,3930 3810,3930 3840,3930 3870,3930 3900,3930 3930,3930 3960,3930 3990,3930 4020,3930 4170,3930 4200,3930 4230,3930 4290,3930 4320,3930 4350,3930 4380,3930 4410,3930 4440,3930 5190,3930 5220,3930 5250,3930 5280,3930 5310,3930 5340,3930 5370,3930 5400,3930 5430,3930 5580,3930 5610,3930 5640,3930 5670,3930 5700,3930 5730,3930 5760,3930 5790,3930 5820,3930 5850,3930 5880,3930 5910,3930 5940,3930 3660,3960 3690,3960 3720,3960 3750,3960 4320,3960 4350,3960 4380,3960 4410,3960 4920,3960 5220,3960 5250,3960 5280,3960 5310,3960 5340,3960 5370,3960 5400,3960 5430,3960 5460,3960 5490,3960 5520,3960 5550,3960 5580,3960 5610,3960 5640,3960 5670,3960 5700,3960 5730,3960 5760,3960 5790,3960 5820,3960 5850,3960 5880,3960 5910,3960 5940,3960 3660,3990 3690,3990 3720,3990 3750,3990 4320,3990 4350,3990 4380,3990 4410,3990 4920,3990 5070,3990 5220,3990 5250,3990 5280,3990 5310,3990 5340,3990 5370,3990 5400,3990 5430,3990 5460,3990 5490,3990 5520,3990 5550,3990 5580,3990 5940,3990 3660,4020 3690,4020 3720,4020 3750,4020 4320,4020 4350,4020 4380,4020 4410,4020 4920,4020 5070,4020 5220,4020 5250,4020 5280,4020 5310,4020 5340,4020 5370,4020 5400,4020 5430,4020 5460,4020 5490,4020 5520,4020 5550,4020 5580,4020 5940,4020 3660,4050 3690,4050 3720,4050 3750,4050 4320,4050 4350,4050 4380,4050 4560,4050 4590,4050 4710,4050 4860,4050 4890,4050 4920,4050 4950,4050 5010,4050 5040,4050 5130,4050 5220,4050 5250,4050 5280,4050 5310,4050 5340,4050 5370,4050 5400,4050 5430,4050 5460,4050 5490,4050 5520,4050 5550,4050 5580,4050 5610,4050 5700,4050 5790,4050 5820,4050 5850,4050 5880,4050 5910,4050 5940,4050 3660,4080 3690,4080 3720,4080 3750,4080 4320,4080 4350,4080 4380,4080 4620,4080 4680,4080 4710,4080 4950,4080 5010,4080 5040,4080 5130,4080 5220,4080 5250,4080 5280,4080 5310,4080 5340,4080 5370,4080 5400,4080 5430,4080 5460,4080 5490,4080 5520,4080 5550,4080 5580,4080 5610,4080 5790,4080 5820,4080 5940,4080 3660,4110 3690,4110 3720,4110 3750,4110 4620,4110 4680,4110 4710,4110 5010,4110 5040,4110 5130,4110 5220,4110 5250,4110 5280,4110 5310,4110 5340,4110 5370,4110 5400,4110 5430,4110 5460,4110 5490,4110 5520,4110 5550,4110 5580,4110 5610,4110 5790,4110 5820,4110 5940,4110 3870,4140 3900,4140 3930,4140 3960,4140 3990,4140 4020,4140 4050,4140 4080,4140 4110,4140 4140,4140 4170,4140 4200,4140 4230,4140 4260,4140 4620,4140 4680,4140 4710,4140 5010,4140 5040,4140 5130,4140 5220,4140 5250,4140 5280,4140 5310,4140 5340,4140 5370,4140 5400,4140 5430,4140 5460,4140 5490,4140 5520,4140 5550,4140 5580,4140 5610,4140 5760,4140 5790,4140 5820,4140 5850,4140 5880,4140 5910,4140 5940,4140 3870,4170 3900,4170 3930,4170 3960,4170 4080,4170 4110,4170 4140,4170 4170,4170 4200,4170 4230,4170 4260,4170 4290,4170 4320,4170 4350,4170 4380,4170 4590,4170 4620,4170 4680,4170 5010,4170 5040,4170 5130,4170 5220,4170 5250,4170 5280,4170 5310,4170 5340,4170 5370,4170 5400,4170 5430,4170 5460,4170 5490,4170 5520,4170 5550,4170 5580,4170 5610,4170 5760,4170 5790,4170 5820,4170 5850,4170 5880,4170 5910,4170 5940,4170 3720,4200 3750,4200 3870,4200 3900,4200 3930,4200 3960,4200 4080,4200 4110,4200 4140,4200 4170,4200 4200,4200 4230,4200 4260,4200 4290,4200 4320,4200 5010,4200 5220,4200 5250,4200 5280,4200 5370,4200 5400,4200 5430,4200 5460,4200 5490,4200 5520,4200 5550,4200 5580,4200 5850,4200 5880,4200 5910,4200 5940,4200 3720,4230 3750,4230 3870,4230 3900,4230 3930,4230 3960,4230 4080,4230 4110,4230 4140,4230 4170,4230 4200,4230 4230,4230 4260,4230 4290,4230 4320,4230 4500,4230 4530,4230 4920,4230 5190,4230 5220,4230 5250,4230 5280,4230 5370,4230 5400,4230 5430,4230 5460,4230 5490,4230 5520,4230 5850,4230 5880,4230 5910,4230 5940,4230 3870,4260 3900,4260 3930,4260 3960,4260 4080,4260 4110,4260 4140,4260 4170,4260 4200,4260 4230,4260 4260,4260 4290,4260 4320,4260 4350,4260 4380,4260 4500,4260 4530,4260 5160,4260 5190,4260 5220,4260 5250,4260 5280,4260 5370,4260 5400,4260 5430,4260 5730,4260 5760,4260 5790,4260 5820,4260 5850,4260 5880,4260 5910,4260 5940,4260 3660,4290 3870,4290 3900,4290 3930,4290 3960,4290 4080,4290 4110,4290 4140,4290 4170,4290 4200,4290 4230,4290 4260,4290 4290,4290 4320,4290 4350,4290 4380,4290 4470,4290 4530,4290 5160,4290 5190,4290 5220,4290 5250,4290 5280,4290 5370,4290 5400,4290 5730,4290 5760,4290 5790,4290 5820,4290 5850,4290 5880,4290 5910,4290 5940,4290 3660,4320 3870,4320 3900,4320 3930,4320 3960,4320 4080,4320 4110,4320 4140,4320 4170,4320 4200,4320 4230,4320 4260,4320 4290,4320 4320,4320 4350,4320 4380,4320 4440,4320 4650,4320 5130,4320 5160,4320 5190,4320 5220,4320 5250,4320 5850,4320 5880,4320 5910,4320 5940,4320 3660,4350 3690,4350 3960,4350 3990,4350 4020,4350 4050,4350 4080,4350 4110,4350 4140,4350 4170,4350 4200,4350 4230,4350 4260,4350 4290,4350 4320,4350 4350,4350 4380,4350 4470,4350 4530,4350 4680,4350 4860,4350 5130,4350 5160,4350 5190,4350 5220,4350 5250,4350 5460,4350 5850,4350 5880,4350 5910,4350 5940,4350 3660,4380 3960,4380 3990,4380 4020,4380 4050,4380 4080,4380 4110,4380 4140,4380 4170,4380 4200,4380 4230,4380 4260,4380 4290,4380 4320,4380 4350,4380 4380,4380 4500,4380 4620,4380 4740,4380 4920,4380 4950,4380 5460,4380 5790,4380 5820,4380 5850,4380 5880,4380 5910,4380 5940,4380 3660,4410 3690,4410 3990,4410 4020,4410 4050,4410 4080,4410 4110,4410 4140,4410 4170,4410 4200,4410 4230,4410 4260,4410 4290,4410 4320,4410 4530,4410 4740,4410 4920,4410 5460,4410 5640,4410 5760,4410 5790,4410 5820,4410 5940,4410 3660,4440 3690,4440 3720,4440 3750,4440 4020,4440 4050,4440 4080,4440 4110,4440 4140,4440 4170,4440 4200,4440 4230,4440 4260,4440 4290,4440 5460,4440 5610,4440 5640,4440 5790,4440 5940,4440 3660,4470 4020,4470 4050,4470 4080,4470 4110,4470 4140,4470 4170,4470 4200,4470 4230,4470 4260,4470 5460,4470 5610,4470 5640,4470 5670,4470 5760,4470 5790,4470 5820,4470 5910,4470 5940,4470 3660,4500 4020,4500 4050,4500 4080,4500 4110,4500 4140,4500 4170,4500 4200,4500 4230,4500 4260,4500 5430,4500 5460,4500 5610,4500 5640,4500 5670,4500 5700,4500 5730,4500 5760,4500 5790,4500 5820,4500 5850,4500 5880,4500 5910,4500 5940,4500 3660,4530 3690,4530 3720,4530 3750,4530 4020,4530 4050,4530 4080,4530 4110,4530 4140,4530 4170,4530 4200,4530 4230,4530 4260,4530 4650,4530 4680,4530 5160,4530 5190,4530 5280,4530 5310,4530 5430,4530 5460,4530 5490,4530 5520,4530 5610,4530 5640,4530 5670,4530 5700,4530 5730,4530 5760,4530 5910,4530 5940,4530 3660,4560 3690,4560 4020,4560 4050,4560 4080,4560 4110,4560 4140,4560 4170,4560 4200,4560 4230,4560 4260,4560 4620,4560 4650,4560 4680,4560 4740,4560 5160,4560 5190,4560 5610,4560 5640,4560 5670,4560 5700,4560 5730,4560 5760,4560 5910,4560 5940,4560 3660,4590 4590,4590 4620,4590 4650,4590 4680,4590 4740,4590 4770,4590 5190,4590 5280,4590 5310,4590 5430,4590 5460,4590 5490,4590 5520,4590 5610,4590 5640,4590 5670,4590 5700,4590 5730,4590 5760,4590 5790,4590 5880,4590 5910,4590 5940,4590 3660,4620 3690,4620 4110,4620 4560,4620 4590,4620 4620,4620 4650,4620 4680,4620 4740,4620 4770,4620 5520,4620 5610,4620 5640,4620 5670,4620 5700,4620 5730,4620 5760,4620 5790,4620 5820,4620 5850,4620 5880,4620 5910,4620 5940,4620 3660,4650 3690,4650 4110,4650 4530,4650 4560,4650 4590,4650 4620,4650 4650,4650 4680,4650 5520,4650 5610,4650 5640,4650 5670,4650 5700,4650 5730,4650 5760,4650 5790,4650 5820,4650 5850,4650 5880,4650 5910,4650 5940,4650 3660,4680 4530,4680 4560,4680 4590,4680 4620,4680 4650,4680 4680,4680 4860,4680 4980,4680 5520,4680 5580,4680 5610,4680 5640,4680 5670,4680 5700,4680 5730,4680 5760,4680 5790,4680 5820,4680 5850,4680 5880,4680 5910,4680 5940,4680 3660,4710 3690,4710 4560,4710 4590,4710 4620,4710 4650,4710 4770,4710 4830,4710 4860,4710 4890,4710 5520,4710 5580,4710 5610,4710 5640,4710 5670,4710 5700,4710 5730,4710 5760,4710 5790,4710 5820,4710 5850,4710 5880,4710 5910,4710 5940,4710 3660,4740 3690,4740 3720,4740 3750,4740 4590,4740 4620,4740 4740,4740 4770,4740 4800,4740 4830,4740 4860,4740 5520,4740 5580,4740 5610,4740 5640,4740 5670,4740 5700,4740 5730,4740 5760,4740 5790,4740 5820,4740 5850,4740 5880,4740 5910,4740 5940,4740 3660,4770 4740,4770 4770,4770 4800,4770 4830,4770 5520,4770 5580,4770 5610,4770 5640,4770 5670,4770 5700,4770 5730,4770 5760,4770 5790,4770 5820,4770 5850,4770 5880,4770 5910,4770 5940,4770 3660,4800 4680,4800 4740,4800 4770,4800 4800,4800 5520,4800 5580,4800 5610,4800 5640,4800 5670,4800 5700,4800 5730,4800 5760,4800 5790,4800 5820,4800 5850,4800 5880,4800 5910,4800 5940,4800 3660,4830 3690,4830 3720,4830 3750,4830 4680,4830 4770,4830 5520,4830 5580,4830 5610,4830 5640,4830 5670,4830 5700,4830 5730,4830 5760,4830 5790,4830 5820,4830 5850,4830 5880,4830 5910,4830 5940,4830 3660,4860 3690,4860 4020,4860 4050,4860 4080,4860 5580,4860 5610,4860 5640,4860 5670,4860 5700,4860 5730,4860 5760,4860 5790,4860 5820,4860 5850,4860 5880,4860 5910,4860 5940,4860 3660,4890 4020,4890 4050,4890 4080,4890 5550,4890 5580,4890 5610,4890 5640,4890 5670,4890 5700,4890 5730,4890 5760,4890 5790,4890 5820,4890 5850,4890 5880,4890 5910,4890 5940,4890 3660,4920 3690,4920 4020,4920 4050,4920 4080,4920 4260,4920 5520,4920 5550,4920 5580,4920 5610,4920 5640,4920 5670,4920 5700,4920 5730,4920 5760,4920 5790,4920 5820,4920 5850,4920 5880,4920 5910,4920 5940,4920 3660,4950 3690,4950 3960,4950 4020,4950 4050,4950 4080,4950 4350,4950 5100,4950 5460,4950 5490,4950 5520,4950 5550,4950 5580,4950 5610,4950 5640,4950 5670,4950 5700,4950 5730,4950 5760,4950 5790,4950 5880,4950 5910,4950 5940,4950 3660,4980 4020,4980 4050,4980 4260,4980 4350,4980 5070,4980 5550,4980 5580,4980 5610,4980 5640,4980 5670,4980 5700,4980 5730,4980 5760,4980 5910,4980 5940,4980 3660,5010 3690,5010 3990,5010 4020,5010 4230,5010 4260,5010 5550,5010 5580,5010 5610,5010 5640,5010 5670,5010 5700,5010 5730,5010 5760,5010 5910,5010 5940,5010 3660,5040 3690,5040 3720,5040 3750,5040 3960,5040 3990,5040 4080,5040 4230,5040 4260,5040 5550,5040 5580,5040 5610,5040 5640,5040 5670,5040 5700,5040 5730,5040 5760,5040 5790,5040 5820,5040 5850,5040 5880,5040 5910,5040 5940,5040 3660,5070 3960,5070 4050,5070 4080,5070 4110,5070 4140,5070 4170,5070 4200,5070 4230,5070 4320,5070 5100,5070 5550,5070 5580,5070 5610,5070 5640,5070 5670,5070 5700,5070 5730,5070 5760,5070 5790,5070 5820,5070 5850,5070 5880,5070 5910,5070 5940,5070 3660,5100 4020,5100 4050,5100 4080,5100 4110,5100 4140,5100 4170,5100 4200,5100 4230,5100 4770,5100 4800,5100 5100,5100 5340,5100 5370,5100 5670,5100 5700,5100 5730,5100 5760,5100 5790,5100 5820,5100 5850,5100 5880,5100 5910,5100 5940,5100 3660,5130 3690,5130 3720,5130 3750,5130 3930,5130 4020,5130 4050,5130 4080,5130 4110,5130 4140,5130 4170,5130 4200,5130 4230,5130 4320,5130 4560,5130 5700,5130 5730,5130 5760,5130 5790,5130 5820,5130 5850,5130 5880,5130 5910,5130 5940,5130 3990,5160 4020,5160 4170,5160 4200,5160 4230,5160 4320,5160 4620,5160 4650,5160 4680,5160 5400,5160 5430,5160 5610,5160 5640,5160 5670,5160 5820,5160 5850,5160 5880,5160 5910,5160 5940,5160 3960,5190 3990,5190 4200,5190 4320,5190 4680,5190 4920,5190 5640,5190 5670,5190 5820,5190 5850,5190 5880,5190 5910,5190 5940,5190 3660,5220 3690,5220 3750,5220 3780,5220 3840,5220 3870,5220 3900,5220 3930,5220 3960,5220 4350,5220 4860,5220 4890,5220 4920,5220 5640,5220 5670,5220 5760,5220 5850,5220 5880,5220 5910,5220 5940,5220 3660,5250 3780,5250 3960,5250 4350,5250 4380,5250 4410,5250 4440,5250 4470,5250 4500,5250 4530,5250 4800,5250 4830,5250 4860,5250 4890,5250 4920,5250 5640,5250 5670,5250 5760,5250 5850,5250 5940,5250 3660,5280 3780,5280 3810,5280 3840,5280 3960,5280 4350,5280 4380,5280 4410,5280 4440,5280 4470,5280 4500,5280 4530,5280 4800,5280 4830,5280 4860,5280 4890,5280 4920,5280 5640,5280 5670,5280 5760,5280 5790,5280 5820,5280 5850,5280 5940,5280 3780,5310 3960,5310 3990,5310 4200,5310 4350,5310 4380,5310 4410,5310 4440,5310 4470,5310 4500,5310 4530,5310 4800,5310 4830,5310 4860,5310 4890,5310 4920,5310 5640,5310 5670,5310 5760,5310 5850,5310 5940,5310
  other v2: 4915,3805 4742.44,3835 3670,4155.34 5325,4232.44 5235,4780 4455,4855 5021.27,4855.02 4515,4905 5015,4940 5040,5185 5095,5185 5095,5220 5040,5230.76
I2C1_SCL: D9.1 U16.2 | length 772.3
  Top Layer w5: 4895.95,4560.81 4950,4506.76 v2@4950,4495 ; v2(4985,4540) 4985,4030 5020,3995 5020,3932.48 5020.4,3932.09
  Bottom Layer w5: v2(4945,4495) 4985,4535 v2(4985,4540)
I2C1_SDA: D8.1 U16.1 | length 668
  Top Layer w5: 4909.86,4574.73 4971.18,4513.41 4971.18,3932.09
I2C2_SCL: D11.1 U17.2 | length 769
  Top Layer w5: v2(4415,4585) 4460.41,4630.41 4464.46,4630.41
  Top Layer w10: v2(4445,4255) 4445,4070 4530.4,3984.61 4530.4,3932.09
  Bottom Layer w10: v2(4415,4585) 4415,4285 v2(4445,4255)
I2C2_SDA: D10.1 U17.1 | length 945.4
  Top Layer w5: 4478.37,4783.51 4520,4741.88 4520,4735 4510,4725 v2(4500,4725)
  Top Layer w10: v2(4460,4385) 4415,4340 4415,4055 4481.18,3988.82 4481.18,3932.09
  Bottom Layer w10: v2(4460,4385) 4500,4425 v2(4500,4725)
KEY:  | length 1129.9
  Top Layer w5: 4464.04,4936.87 4464.56,4936.35 v2(4464.56,4885) ; v2(4490,4885) 4490,4883.24 4534.05,4839.19
  Top Layer w10: 3724.4,5280 3725,5279.4 v2(3725,5180)
  Bottom Layer w5: v2(3725,5180) 3930,5180 3975,5135 3975,5090 4180,4885 v2(4464.56,4885) v2(4490,4885)
OSC_IN: C79.1 | length 323.8
  Top Layer w5: 4923.79,4811.35 4952.44,4840 4970,4840 5025.51,4784.49 C79.1@5060.51,4784.49 5105,4828.98 5105,4865 5069.98,4900.02 5069.98,4903.73
OSC_OUT:  | length 111.8
  Top Layer w10: 4909.86,4825.27 4957.56,4872.97 v2(4957.56,4875) 4960.02,4877.46 4960.02,4916.27
RST:  | length 1421.7
  Top Layer w5: 4895.95,4839.19 4925,4868.24 4925,4890 4905,4910 4905,4925 4975,4995 4975,5015 4940,5050 4940,5075 4955,5090 v2(5070,5090) ; v2(5175,5260) 5235,5260 5375,5120 5660,5120 5712.44,5172.44 5712.44,5175
  Top Layer w10: 5712.44,5175 5714.4,5176.96 5714.4,5280
  Bottom Layer w5: v2(5070,5090) 5070,5235 5095,5260 v2(5175,5260)
SER.1:  | length 384.9
  Top Layer w5: 3888.38,4385 3888.38,4413.38 cw(c3900,4413.38) 3900,4425 3955,4425 ccw(c3955,4450) 3980,4450 3980,4620 cw(c4000,4620) 4000,4640 4040.95,4640 ccw(c4040.95,4641.02) 4041.97,4641.02
SER.2:  | length 308.1
  Top Layer w5: 3888.38,4485 3888.38,4518.38 cw(c3900,4518.38) 3900,4530 3935,4530 ccw(c3935,4555) 3960,4555 3960,4640 cw(c3985,4640) 3985,4665 4040.36,4665 ccw(c4040.36,4666.61) 4041.97,4666.61
SER.3:  | length 242
  Top Layer w5: 3888.38,4585 3888.38,4613.38 cw(c3900,4613.38) 3900,4625 3925,4625 ccw(c3925,4645) 3945,4645 3945,4680 cw(c3957.21,4680) 3957.21,4692.21 4041.97,4692.21
SER.4:  | length 184.9
  Top Layer w5: 3888.38,4685 3888.38,4708.38 cw(c3900,4708.38) 3900,4720 4039.77,4720 cw(c4039.77,4717.8) 4041.97,4717.8
SER.5:  | length 189.3
  Top Layer w5: 3888.74,4785 cw(c3888.74,4783.74) 3890,4783.74 3890,4755 ccw(c3901.61,4755) 3901.61,4743.39 4041.97,4743.39
SER.5V: C10.1 L1.2 U18.2 U19.2 U20.2 U21.2 U22.2 U23.2 U24.2 U25.2 | length 604.3
  Bottom Layer w10: 4240.5,4035 cw(c4240.5,4020.5) 4255,4020.5 4255,3830 ccw(c4300,3830) 4300,3785 4620.34,3785
  other v2: 4195,3980 4195,4007.5 4195,4035 4195,4062.5 4195,4090
SER.6:  | length 238.4
  Top Layer w5: 3888.38,4885 3888.38,4851.62 ccw(c3900,4851.62) 3900,4840 cw(c3900,4800) 3940,4800 3940,4790 ccw(c3960,4790) 3960,4770 4040.95,4770 cw(c4040.95,4768.98) 4041.97,4768.98
SER.7:  | length 310.7
  Top Layer w5: 3888.74,4985 cw(c3888.74,4983.74) 3890,4983.74 3890,4945 ccw(c3905,4945) 3905,4930 3930,4930 cw(c3930,4900) 3960,4900 3960,4825 ccw(c3990.43,4825) 3990.43,4794.57 4041.97,4794.57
